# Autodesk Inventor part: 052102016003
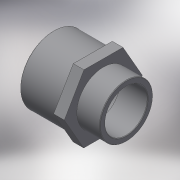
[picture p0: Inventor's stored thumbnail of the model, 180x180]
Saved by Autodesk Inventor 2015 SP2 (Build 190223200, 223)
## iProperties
Created: 2017-10
Part Number: 052102016003
Material: Generic
Description: PLASSON SOCKET NIPPLE THR-CE 20(16)-3/8"
Document SubType Name: Modeling
Designer: KIM
Density: 1 g/cm^3
Appearance: Default
Author: KIM
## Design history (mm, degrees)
derived "052102.ipt"
feature "Solid1::052102.ipt"
tag "TaggingFeature1"
body "Solid1"
other parameters: "d2" = 22, "d13" = 0, "d14" = 0.16, "d17" = 16, "d18" = 13.2, "d20" = 16, "d21" = 16.662, "d22" = 14, "d23" = 15.2, "d24" = 13.3296, "d25" = 11, "d26" = -16, "d_" = 16, "R_" = 16.662, "C_" = 22, "B_" = 12, "L_" = 16, "lt_" = 11, "l_" = 14
